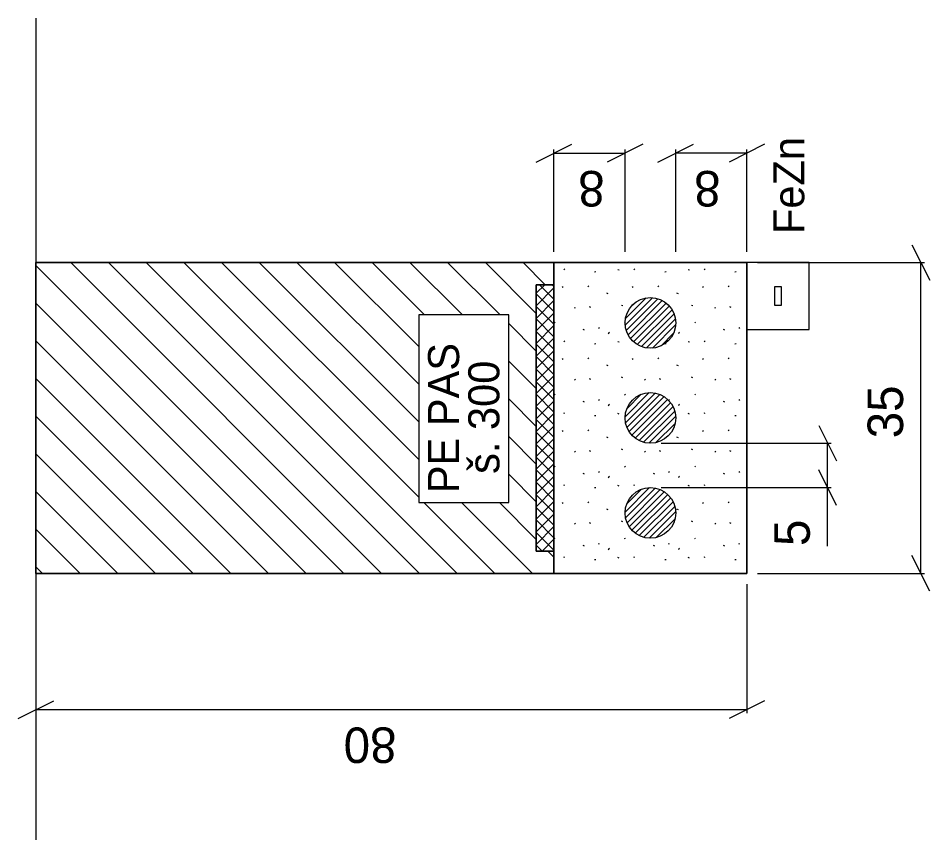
# Model space of a CAD drawing. Extents: x -762592 to -762444, y -1032635 to -1032425.
# Drawn here: x -762577.49 to -762561.07, y -1032613.49 to -1032598.69 of the extents above; entities that cross this region are included whole.
import ezdxf

# ---------------------------------------------------------------- set-up
doc = ezdxf.new("R2010")
doc.units = 0
for name, color, linetype in [('Kabeláž - kabelové vedení HDV - stávající', 7, 'Continuous'), ('X ŘEZY TRASOU', 7, 'Continuous'), ('X ŘEZY TRASOU - KÓTY', 7, 'Continuous'), ('X ŘEZY TRASOU - ŠRAFY', 7, 'Continuous')]:
    doc.layers.add(name, color=color, linetype=linetype)

msp = doc.modelspace()

# ---------------------------------------------------------------- linework, layer by layer
at = {"layer": 'Kabeláž - kabelové vedení HDV - stávající'}
for p, q in [((-762566.558, -1032604.221), (-762566.064, -1032603.727)), ((-762566.553, -1032604.103), (-762566.182, -1032603.731)), ((-762566.54, -1032604.316), (-762565.97, -1032603.746)), ((-762566.506, -1032604.395), (-762565.89, -1032603.779)), ((-762566.461, -1032604.463), (-762565.822, -1032603.824)), ((-762566.46, -1032603.897), (-762566.387, -1032603.823)), ((-762566.407, -1032604.522), (-762565.764, -1032603.879)), ((-762566.341, -1032604.57), (-762565.715, -1032603.944)), ((-762566.265, -1032604.607), (-762565.679, -1032604.02)), ((-762566.176, -1032604.63), (-762565.654, -1032604.109)), ((-762566.066, -1032604.634), (-762565.651, -1032604.219)), ((-762565.912, -1032604.593), (-762565.693, -1032604.374)), ((-762566.559, -1032605.873), (-762566.124, -1032605.437)), ((-762566.552, -1032605.979), (-762566.019, -1032605.445)), ((-762566.53, -1032605.73), (-762566.268, -1032605.468)), ((-762566.526, -1032606.065), (-762565.932, -1032605.471)), ((-762566.487, -1032606.14), (-762565.858, -1032605.51)), ((-762566.438, -1032606.203), (-762565.794, -1032605.559)), ((-762566.378, -1032606.257), (-762565.741, -1032605.619)), ((-762566.308, -1032606.3), (-762565.697, -1032605.689)), ((-762566.226, -1032606.331), (-762565.666, -1032605.771)), ((-762566.13, -1032606.348), (-762565.65, -1032605.868)), ((-762566.005, -1032606.337), (-762565.66, -1032605.992)), ((-762566.56, -1032607.588), (-762566.12, -1032607.149)), ((-762566.552, -1032607.693), (-762566.016, -1032607.158)), ((-762566.533, -1032607.448), (-762566.262, -1032607.178)), ((-762566.525, -1032607.78), (-762565.93, -1032607.184)), ((-762566.486, -1032607.854), (-762565.856, -1032607.224)), ((-762566.436, -1032607.917), (-762565.792, -1032607.273)), ((-762566.376, -1032607.97), (-762565.739, -1032607.333)), ((-762566.306, -1032608.014), (-762565.696, -1032607.404)), ((-762566.223, -1032608.044), (-762565.665, -1032607.486)), ((-762566.126, -1032608.06), (-762565.65, -1032607.584)), ((-762566.001, -1032608.048), (-762565.661, -1032607.708))]:
    msp.add_line(p, q, dxfattribs=at)
at = {"layer": 'X ŘEZY TRASOU'}
for p, q in [((-762577.169, -1032598.693), (-762577.169, -1032603.093)), ((-762577.169, -1032608.693), (-762577.169, -1032603.093)), ((-762577.169, -1032603.093), (-762567.841, -1032603.093)), ((-762567.841, -1032603.093), (-762567.841, -1032608.693)), ((-762567.841, -1032608.693), (-762567.841, -1032603.093)), ((-762567.841, -1032603.093), (-762564.369, -1032603.093)), ((-762564.369, -1032603.093), (-762564.369, -1032608.693)), ((-762564.369, -1032603.093), (-762564.369, -1032604.302)), ((-762563.247, -1032603.093), (-762564.369, -1032603.093)), ((-762563.247, -1032604.302), (-762563.247, -1032603.093)), ((-762568.161, -1032608.293), (-762568.161, -1032603.493)), ((-762568.161, -1032603.493), (-762567.841, -1032603.493)), ((-762568.161, -1032603.646), (-762568.007, -1032603.493)), ((-762567.841, -1032603.493), (-762568.161, -1032603.493)), ((-762568.161, -1032603.493), (-762568.161, -1032608.293)), ((-762568.161, -1032603.872), (-762567.841, -1032603.552)), ((-762567.841, -1032603.752), (-762568.1, -1032603.493)), ((-762567.841, -1032603.525), (-762567.873, -1032603.493)), ((-762567.841, -1032603.493), (-762567.841, -1032608.293)), ((-762567.841, -1032608.293), (-762567.841, -1032603.493)), ((-762563.863, -1032603.869), (-762563.863, -1032603.526)), ((-762563.863, -1032603.526), (-762563.752, -1032603.526)), ((-762563.752, -1032603.526), (-762563.752, -1032603.869)), ((-762567.841, -1032603.978), (-762568.161, -1032603.658)), ((-762568.161, -1032604.099), (-762567.841, -1032603.779)), ((-762567.841, -1032604.204), (-762568.161, -1032603.884)), ((-762563.752, -1032603.869), (-762563.863, -1032603.869)), ((-762568.161, -1032604.325), (-762567.841, -1032604.005)), ((-762567.841, -1032604.43), (-762568.161, -1032604.11)), ((-762568.161, -1032604.551), (-762567.841, -1032604.231)), ((-762567.841, -1032604.657), (-762568.161, -1032604.337)), ((-762564.369, -1032604.302), (-762563.247, -1032604.302)), ((-762568.161, -1032604.778), (-762567.841, -1032604.458)), ((-762567.841, -1032604.883), (-762568.161, -1032604.563)), ((-762568.161, -1032605.004), (-762567.841, -1032604.684)), ((-762567.841, -1032605.109), (-762568.161, -1032604.789)), ((-762568.161, -1032605.23), (-762567.841, -1032604.91)), ((-762567.841, -1032605.336), (-762568.161, -1032605.016)), ((-762568.161, -1032605.456), (-762567.841, -1032605.136)), ((-762567.841, -1032605.562), (-762568.161, -1032605.242)), ((-762568.161, -1032605.683), (-762567.841, -1032605.363)), ((-762567.841, -1032605.788), (-762568.161, -1032605.468)), ((-762568.161, -1032605.909), (-762567.841, -1032605.589)), ((-762567.841, -1032606.014), (-762568.161, -1032605.694)), ((-762568.161, -1032606.135), (-762567.841, -1032605.815)), ((-762567.841, -1032606.241), (-762568.161, -1032605.921)), ((-762568.161, -1032606.361), (-762567.841, -1032606.041)), ((-762567.841, -1032606.467), (-762568.161, -1032606.147)), ((-762568.161, -1032606.588), (-762567.841, -1032606.268)), ((-762567.841, -1032606.693), (-762568.161, -1032606.373)), ((-762568.161, -1032606.814), (-762567.841, -1032606.494)), ((-762567.841, -1032606.919), (-762568.161, -1032606.599)), ((-762568.161, -1032607.04), (-762567.841, -1032606.72)), ((-762567.841, -1032607.146), (-762568.161, -1032606.826)), ((-762568.161, -1032607.267), (-762567.841, -1032606.947)), ((-762567.841, -1032607.372), (-762568.161, -1032607.052)), ((-762568.161, -1032607.493), (-762567.841, -1032607.173)), ((-762567.841, -1032607.598), (-762568.161, -1032607.278)), ((-762568.161, -1032607.719), (-762567.841, -1032607.399)), ((-762567.841, -1032607.825), (-762568.161, -1032607.505)), ((-762568.161, -1032607.945), (-762567.841, -1032607.625)), ((-762567.841, -1032608.051), (-762568.161, -1032607.731)), ((-762568.161, -1032608.172), (-762567.841, -1032607.852)), ((-762567.841, -1032608.277), (-762568.161, -1032607.957)), ((-762568.051, -1032608.293), (-762568.161, -1032608.183)), ((-762568.055, -1032608.293), (-762567.841, -1032608.078)), ((-762567.841, -1032608.293), (-762568.161, -1032608.293)), ((-762568.161, -1032608.293), (-762567.841, -1032608.293)), ((-762577.169, -1032608.693), (-762577.169, -1032613.493)), ((-762567.841, -1032608.693), (-762577.169, -1032608.693)), ((-762564.369, -1032608.693), (-762567.841, -1032608.693)), ((-762577.169, -1032610.293), (-762577.169, -1032612.587))]:
    msp.add_line(p, q, dxfattribs=at)
for centre in [(-762566.105, -1032604.181), (-762566.105, -1032605.893), (-762566.105, -1032607.605)]:
    msp.add_circle(centre, 0.456, dxfattribs=at)
at = {"layer": 'X ŘEZY TRASOU - KÓTY'}
for p, q in [((-762568.161, -1032601.284), (-762567.521, -1032600.964)), ((-762567.841, -1032602.901), (-762567.841, -1032601.06)), ((-762567.841, -1032601.124), (-762566.561, -1032601.124)), ((-762566.241, -1032600.964), (-762566.881, -1032601.284)), ((-762566.561, -1032602.901), (-762566.561, -1032601.06)), ((-762565.969, -1032601.284), (-762565.329, -1032600.964)), ((-762565.649, -1032602.901), (-762565.649, -1032601.06)), ((-762564.369, -1032601.124), (-762565.649, -1032601.124)), ((-762564.049, -1032600.964), (-762564.689, -1032601.284)), ((-762564.369, -1032602.901), (-762564.369, -1032601.06)), ((-762561.394, -1032602.773), (-762561.074, -1032603.413)), ((-762564.177, -1032603.093), (-762561.17, -1032603.093)), ((-762561.234, -1032608.693), (-762561.234, -1032603.093)), ((-762563.074, -1032606.029), (-762562.754, -1032606.669)), ((-762565.913, -1032606.349), (-762562.85, -1032606.349)), ((-762562.914, -1032607.149), (-762562.914, -1032606.349)), ((-762562.754, -1032607.469), (-762563.074, -1032606.829)), ((-762565.913, -1032607.149), (-762562.85, -1032607.149)), ((-762562.914, -1032608.201), (-762562.914, -1032607.149)), ((-762561.074, -1032609.013), (-762561.394, -1032608.373)), ((-762564.177, -1032608.693), (-762561.17, -1032608.693)), ((-762577.169, -1032608.885), (-762577.169, -1032611.213)), ((-762564.369, -1032608.885), (-762564.369, -1032611.213)), ((-762577.489, -1032611.309), (-762576.849, -1032610.989)), ((-762564.049, -1032610.989), (-762564.689, -1032611.309)), ((-762564.369, -1032611.149), (-762577.169, -1032611.149))]:
    msp.add_line(p, q, dxfattribs=at)
at = {"layer": 'X ŘEZY TRASOU - ŠRAFY'}
for p, q in [((-762570.944, -1032608.693), (-762576.544, -1032603.093)), ((-762570.265, -1032608.693), (-762575.865, -1032603.093)), ((-762569.586, -1032608.693), (-762575.186, -1032603.093)), ((-762570.277, -1032607.323), (-762574.507, -1032603.093)), ((-762570.277, -1032606.644), (-762573.829, -1032603.093)), ((-762570.277, -1032605.965), (-762573.15, -1032603.093)), ((-762570.277, -1032605.287), (-762572.471, -1032603.093)), ((-762570.277, -1032604.608), (-762571.792, -1032603.093)), ((-762570.17, -1032604.036), (-762571.113, -1032603.093)), ((-762569.491, -1032604.036), (-762570.434, -1032603.093)), ((-762568.812, -1032604.036), (-762569.756, -1032603.093)), ((-762568.161, -1032604.009), (-762569.077, -1032603.093)), ((-762567.998, -1032603.493), (-762568.398, -1032603.093)), ((-762567.841, -1032603.493), (-762567.841, -1032603.093)), ((-762564.369, -1032603.093), (-762567.841, -1032603.093)), ((-762567.841, -1032603.093), (-762567.841, -1032603.493)), ((-762571.623, -1032608.693), (-762577.169, -1032603.147)), ((-762567.665, -1032603.217), (-762567.648, -1032603.207)), ((-762567.112, -1032603.259), (-762567.087, -1032603.256)), ((-762566.665, -1032603.234), (-762566.689, -1032603.223)), ((-762566.4, -1032603.217), (-762566.384, -1032603.207)), ((-762565.847, -1032603.259), (-762565.823, -1032603.256)), ((-762565.401, -1032603.234), (-762565.425, -1032603.223)), ((-762565.136, -1032603.217), (-762565.12, -1032603.207)), ((-762564.583, -1032603.259), (-762564.559, -1032603.256)), ((-762567.841, -1032603.493), (-762567.841, -1032608.293)), ((-762567.694, -1032603.537), (-762567.678, -1032603.526)), ((-762567.232, -1032603.527), (-762567.216, -1032603.516)), ((-762566.43, -1032603.537), (-762566.413, -1032603.526)), ((-762565.968, -1032603.527), (-762565.951, -1032603.516)), ((-762565.165, -1032603.537), (-762565.149, -1032603.526)), ((-762564.703, -1032603.527), (-762564.687, -1032603.516)), ((-762566.866, -1032603.656), (-762566.89, -1032603.646)), ((-762565.601, -1032603.656), (-762565.626, -1032603.646)), ((-762572.301, -1032608.693), (-762577.169, -1032603.825)), ((-762567.472, -1032603.912), (-762567.456, -1032603.901)), ((-762567.18, -1032603.903), (-762567.204, -1032603.892)), ((-762566.603, -1032603.876), (-762566.627, -1032603.865)), ((-762565.338, -1032603.876), (-762565.363, -1032603.865)), ((-762564.944, -1032603.912), (-762564.927, -1032603.901)), ((-762564.651, -1032603.903), (-762564.675, -1032603.892)), ((-762568.656, -1032604.036), (-762570.277, -1032604.036)), ((-762570.277, -1032604.036), (-762570.277, -1032607.417)), ((-762568.656, -1032607.417), (-762568.656, -1032604.036)), ((-762568.161, -1032604.688), (-762568.656, -1032604.192)), ((-762567.835, -1032604.179), (-762567.819, -1032604.168)), ((-762566.571, -1032604.179), (-762566.56, -1032604.171)), ((-762565.307, -1032604.179), (-762565.291, -1032604.168)), ((-762567.291, -1032604.314), (-762567.315, -1032604.303)), ((-762567.04, -1032604.275), (-762567.024, -1032604.264)), ((-762566.866, -1032604.371), (-762566.849, -1032604.36)), ((-762566.859, -1032604.36), (-762566.843, -1032604.349)), ((-762565.601, -1032604.371), (-762565.585, -1032604.36)), ((-762565.595, -1032604.36), (-762565.579, -1032604.349)), ((-762564.762, -1032604.314), (-762564.786, -1032604.303)), ((-762564.511, -1032604.275), (-762564.495, -1032604.264)), ((-762572.98, -1032608.693), (-762577.169, -1032604.504)), ((-762567.665, -1032604.514), (-762567.648, -1032604.503)), ((-762567.112, -1032604.556), (-762567.087, -1032604.553)), ((-762566.665, -1032604.531), (-762566.689, -1032604.52)), ((-762565.845, -1032604.555), (-762565.823, -1032604.553)), ((-762565.401, -1032604.531), (-762565.425, -1032604.52)), ((-762565.136, -1032604.514), (-762565.12, -1032604.503)), ((-762564.583, -1032604.556), (-762564.559, -1032604.553)), ((-762568.161, -1032605.366), (-762568.656, -1032604.871)), ((-762567.694, -1032604.834), (-762567.678, -1032604.823)), ((-762567.232, -1032604.824), (-762567.216, -1032604.813)), ((-762566.43, -1032604.834), (-762566.413, -1032604.823)), ((-762565.968, -1032604.824), (-762565.951, -1032604.813)), ((-762565.165, -1032604.834), (-762565.149, -1032604.823)), ((-762564.703, -1032604.824), (-762564.687, -1032604.813)), ((-762566.866, -1032604.953), (-762566.89, -1032604.942)), ((-762565.601, -1032604.953), (-762565.626, -1032604.942)), ((-762573.659, -1032608.693), (-762577.169, -1032605.183)), ((-762567.472, -1032605.208), (-762567.456, -1032605.197)), ((-762567.18, -1032605.199), (-762567.204, -1032605.188)), ((-762566.603, -1032605.172), (-762566.627, -1032605.161)), ((-762566.208, -1032605.208), (-762566.192, -1032605.197)), ((-762565.915, -1032605.199), (-762565.94, -1032605.188)), ((-762565.338, -1032605.172), (-762565.363, -1032605.161)), ((-762564.944, -1032605.208), (-762564.927, -1032605.197)), ((-762564.651, -1032605.199), (-762564.675, -1032605.188)), ((-762568.161, -1032606.045), (-762568.656, -1032605.55)), ((-762567.835, -1032605.475), (-762567.819, -1032605.464)), ((-762566.571, -1032605.475), (-762566.555, -1032605.464)), ((-762565.307, -1032605.475), (-762565.291, -1032605.464)), ((-762567.291, -1032605.611), (-762567.315, -1032605.6)), ((-762567.04, -1032605.571), (-762567.024, -1032605.56)), ((-762566.866, -1032605.667), (-762566.849, -1032605.657)), ((-762566.859, -1032605.657), (-762566.843, -1032605.646)), ((-762565.776, -1032605.571), (-762565.759, -1032605.56)), ((-762565.601, -1032605.667), (-762565.585, -1032605.657)), ((-762565.595, -1032605.657), (-762565.579, -1032605.646)), ((-762564.762, -1032605.611), (-762564.786, -1032605.6)), ((-762564.511, -1032605.571), (-762564.495, -1032605.56)), ((-762574.338, -1032608.693), (-762577.169, -1032605.862)), ((-762567.665, -1032605.81), (-762567.648, -1032605.8)), ((-762567.112, -1032605.852), (-762567.087, -1032605.85)), ((-762566.665, -1032605.827), (-762566.689, -1032605.816)), ((-762565.401, -1032605.827), (-762565.425, -1032605.816)), ((-762565.136, -1032605.81), (-762565.12, -1032605.8)), ((-762564.583, -1032605.852), (-762564.559, -1032605.85)), ((-762567.694, -1032606.13), (-762567.678, -1032606.12)), ((-762567.232, -1032606.12), (-762567.216, -1032606.109)), ((-762565.165, -1032606.13), (-762565.149, -1032606.12)), ((-762564.703, -1032606.12), (-762564.687, -1032606.109)), ((-762568.161, -1032606.724), (-762568.656, -1032606.229)), ((-762566.866, -1032606.249), (-762566.89, -1032606.239)), ((-762565.601, -1032606.249), (-762565.626, -1032606.239)), ((-762575.017, -1032608.693), (-762577.169, -1032606.541)), ((-762567.472, -1032606.505), (-762567.456, -1032606.494)), ((-762567.18, -1032606.496), (-762567.204, -1032606.485)), ((-762566.603, -1032606.469), (-762566.627, -1032606.458)), ((-762566.208, -1032606.505), (-762566.192, -1032606.494)), ((-762565.915, -1032606.496), (-762565.94, -1032606.485)), ((-762565.338, -1032606.469), (-762565.363, -1032606.458)), ((-762564.944, -1032606.505), (-762564.927, -1032606.494)), ((-762564.651, -1032606.496), (-762564.675, -1032606.485)), ((-762567.835, -1032606.772), (-762567.819, -1032606.761)), ((-762567.04, -1032606.868), (-762567.024, -1032606.857)), ((-762566.571, -1032606.772), (-762566.555, -1032606.761)), ((-762565.776, -1032606.868), (-762565.759, -1032606.857)), ((-762565.307, -1032606.772), (-762565.291, -1032606.761)), ((-762564.511, -1032606.868), (-762564.495, -1032606.857)), ((-762568.161, -1032607.403), (-762568.656, -1032606.907)), ((-762567.291, -1032606.907), (-762567.315, -1032606.896)), ((-762566.866, -1032606.964), (-762566.849, -1032606.953)), ((-762566.859, -1032606.953), (-762566.843, -1032606.942)), ((-762566.026, -1032606.907), (-762566.051, -1032606.896)), ((-762565.601, -1032606.964), (-762565.585, -1032606.953)), ((-762565.595, -1032606.953), (-762565.579, -1032606.942)), ((-762564.762, -1032606.907), (-762564.786, -1032606.896)), ((-762567.665, -1032607.107), (-762567.648, -1032607.096)), ((-762567.112, -1032607.149), (-762567.087, -1032607.146)), ((-762566.665, -1032607.124), (-762566.689, -1032607.113)), ((-762566.4, -1032607.107), (-762566.384, -1032607.096)), ((-762565.847, -1032607.149), (-762565.823, -1032607.146)), ((-762565.401, -1032607.124), (-762565.425, -1032607.113)), ((-762565.136, -1032607.107), (-762565.12, -1032607.096)), ((-762564.583, -1032607.149), (-762564.559, -1032607.146)), ((-762575.696, -1032608.693), (-762577.169, -1032607.22)), ((-762570.277, -1032607.417), (-762568.656, -1032607.417)), ((-762568.907, -1032608.693), (-762570.183, -1032607.417)), ((-762568.229, -1032608.693), (-762569.504, -1032607.417)), ((-762568.161, -1032608.082), (-762568.825, -1032607.417)), ((-762567.694, -1032607.427), (-762567.678, -1032607.416)), ((-762567.232, -1032607.417), (-762567.216, -1032607.406)), ((-762565.165, -1032607.427), (-762565.149, -1032607.416)), ((-762564.703, -1032607.417), (-762564.687, -1032607.406)), ((-762566.866, -1032607.546), (-762566.89, -1032607.535)), ((-762565.601, -1032607.546), (-762565.626, -1032607.535)), ((-762567.472, -1032607.801), (-762567.456, -1032607.79)), ((-762567.18, -1032607.792), (-762567.204, -1032607.781)), ((-762566.603, -1032607.765), (-762566.627, -1032607.754)), ((-762565.338, -1032607.765), (-762565.363, -1032607.754)), ((-762564.944, -1032607.801), (-762564.927, -1032607.79)), ((-762564.651, -1032607.792), (-762564.675, -1032607.781)), ((-762576.374, -1032608.693), (-762577.169, -1032607.898)), ((-762567.835, -1032608.068), (-762567.819, -1032608.057)), ((-762567.04, -1032608.164), (-762567.024, -1032608.153)), ((-762566.571, -1032608.068), (-762566.555, -1032608.057)), ((-762565.776, -1032608.164), (-762565.759, -1032608.153)), ((-762565.307, -1032608.068), (-762565.291, -1032608.057)), ((-762564.511, -1032608.164), (-762564.495, -1032608.153)), ((-762567.841, -1032608.402), (-762567.95, -1032608.293)), ((-762567.841, -1032608.693), (-762567.841, -1032608.293)), ((-762567.291, -1032608.204), (-762567.315, -1032608.193)), ((-762566.866, -1032608.261), (-762566.849, -1032608.25)), ((-762566.859, -1032608.25), (-762566.843, -1032608.239)), ((-762566.026, -1032608.204), (-762566.051, -1032608.193)), ((-762565.601, -1032608.261), (-762565.585, -1032608.25)), ((-762565.595, -1032608.25), (-762565.579, -1032608.239)), ((-762564.762, -1032608.204), (-762564.786, -1032608.193)), ((-762567.665, -1032608.404), (-762567.648, -1032608.393)), ((-762567.112, -1032608.445), (-762567.087, -1032608.443)), ((-762566.665, -1032608.42), (-762566.689, -1032608.409)), ((-762566.4, -1032608.404), (-762566.384, -1032608.393)), ((-762565.847, -1032608.445), (-762565.823, -1032608.443)), ((-762565.401, -1032608.42), (-762565.425, -1032608.409)), ((-762565.136, -1032608.404), (-762565.12, -1032608.393)), ((-762564.583, -1032608.445), (-762564.559, -1032608.443)), ((-762577.053, -1032608.693), (-762577.169, -1032608.577))]:
    msp.add_line(p, q, dxfattribs=at)
for points in [[(-762567.841, -1032603.093), (-762577.169, -1032603.093), (-762577.169, -1032608.693), (-762567.841, -1032608.693)], [(-762567.841, -1032608.293), (-762567.841, -1032608.693), (-762564.369, -1032608.693), (-762564.369, -1032604.302), (-762564.369, -1032603.093)], [(-762567.841, -1032608.293), (-762568.161, -1032608.293), (-762568.161, -1032603.493), (-762567.841, -1032603.493)]]:
    msp.add_lwpolyline(points, dxfattribs=at)
for centre in [(-762566.105, -1032604.181), (-762566.105, -1032605.893), (-762566.105, -1032607.605)]:
    msp.add_circle(centre, 0.456, dxfattribs=at)

# ---------------------------------------------------------------- texts
at = {"layer": 'X ŘEZY TRASOU'}
for s, p in [('FeZn', (-762563.333, -1032602.58)), ('PE PAS ', (-762569.549, -1032607.249)), ('š. 300', (-762568.824, -1032606.902))]:
    msp.add_text(s, height=0.56, rotation=90, dxfattribs=at).set_placement(p)
at = {"layer": 'X ŘEZY TRASOU - KÓTY'}
for s, rotation, p in [('8', 180, (-762566.929, -1032601.444)), ('8', 180, (-762564.841, -1032601.444)), ('35', 90, (-762561.554, -1032606.26)), ('5', 90, (-762563.234, -1032608.201)), ('80', 180, (-762570.677, -1032611.469))]:
    msp.add_text(s, height=0.64, rotation=rotation, dxfattribs=at).set_placement(p)

doc.saveas('drawing.dxf')
